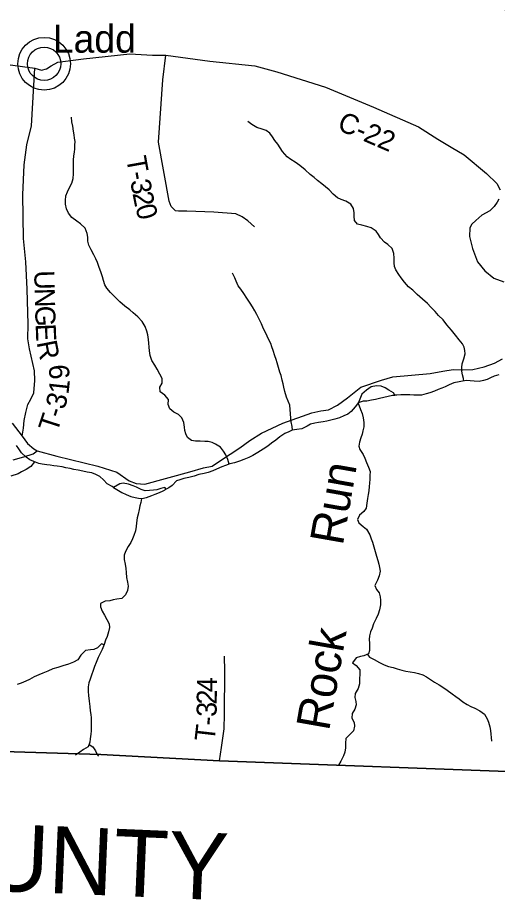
# Model space of a CAD drawing. Extents: x 1578669 to 1989827, y 208020 to 553079.
# Drawn here: x 1774582 to 1781742, y 347821 to 360980 of the extents above; entities that cross this region are included whole.
import ezdxf

# ---------------------------------------------------------------- set-up
doc = ezdxf.new("R2010")
doc.units = 0
for name, color, linetype in [('GM_X_Adjacent_County', 7, 'Continuous'), ('GM_X_Adjacent_County_Text', 7, 'Continuous'), ('GM_X_County', 7, 'Continuous'), ('GM_X_County_Road', 7, 'Continuous'), ('GM_X_County_Road_Text', 7, 'Continuous'), ('GM_X_Minor_River', 7, 'Continuous'), ('GM_X_Minor_River_Text', 7, 'Continuous'), ('GM_X_Township', 7, 'Continuous'), ('GM_X_Township_Road', 7, 'Continuous'), ('GM_X_Township_Road_Text', 7, 'Continuous'), ('GM_X_Unincorporated', 7, 'Continuous'), ('GM_X_Unincorporated_Location', 7, 'Continuous'), ('GM_X_Unincorporated_Text', 7, 'Continuous')]:
    doc.layers.add(name, color=color, linetype=linetype)

msp = doc.modelspace()

# ---------------------------------------------------------------- linework, layer by layer
at = {"layer": 'GM_X_Adjacent_County'}
msp.add_lwpolyline([(1771775, 350107), (1775822, 349984), (1777594, 349890), (1782423, 349710)], dxfattribs=at)
at = {"layer": 'GM_X_County'}
msp.add_lwpolyline([(1782423, 349710), (1777594, 349890), (1775822, 349984), (1771775, 350107)], dxfattribs=at)
at = {"layer": 'GM_X_County_Road'}
for points in [[(1774362, 360289), (1774838, 360225), (1774939, 360195), (1775012, 360218), (1775085, 360260), (1775180, 360315), (1775564, 360363), (1776256, 360441), (1776595, 360422), (1776794, 360418), (1777452, 360331), (1778122, 360260), (1778451, 360172), (1779178, 359940), (1779891, 359642), (1780563, 359349), (1780851, 359167), (1781051, 359047), (1781247, 358934), (1781582, 358654), (1781733, 358504), (1781786, 358411)], [(1781765, 358271), (1781741, 358225), (1781694, 358161), (1781631, 358097), (1781510, 358032), (1781419, 357953), (1781362, 357899), (1781329, 357843), (1781328, 357713), (1781369, 357536), (1781445, 357338), (1781553, 357199), (1781688, 357093), (1781838, 357039)]]:
    msp.add_lwpolyline(points, dxfattribs=at)
at = {"layer": 'GM_X_Minor_River'}
for points in [[(1777737, 354316), (1777739, 354316), (1777721, 354385), (1777690, 354455), (1777654, 354508), (1777609, 354570), (1777537, 354615), (1777483, 354639), (1777425, 354654), (1777375, 354654), (1777307, 354659), (1777239, 354659), (1777175, 354668), (1777117, 354715), (1777092, 354767), (1777076, 354819), (1777075, 354869), (1777063, 354938), (1777032, 355008), (1776982, 355059), (1776914, 355093), (1776853, 355142), (1776827, 355208), (1776832, 355280), (1776780, 355345), (1776707, 355394), (1776705, 355464), (1776740, 355524), (1776738, 355596), (1776705, 355660), (1776665, 355733), (1776628, 355795), (1776586, 355864), (1776561, 355936), (1776550, 356007), (1776546, 356061), (1776539, 356123), (1776535, 356177), (1776526, 356247), (1776512, 356302), (1776487, 356372), (1776443, 356447), (1776376, 356517), (1776308, 356576), (1776256, 356617), (1776181, 356675), (1776105, 356740), (1776034, 356811), (1775966, 356876), (1775913, 356942), (1775885, 356993), (1775864, 357057), (1775848, 357111), (1775825, 357188), (1775801, 357252), (1775772, 357324), (1775750, 357379), (1775721, 357441), (1775679, 357514), (1775644, 357584), (1775632, 357646), (1775629, 357705), (1775621, 357759), (1775588, 357837), (1775520, 357902), (1775467, 357941), (1775393, 357999), (1775339, 358062), (1775310, 358128), (1775297, 358195), (1775295, 358253), (1775302, 358321), (1775324, 358381), (1775351, 358433), (1775389, 358511), (1775410, 358579), (1775416, 358649), (1775415, 358719), (1775416, 358783), (1775414, 358851), (1775423, 358919), (1775433, 358974), (1775436, 359024), (1775438, 359076), (1775439, 359130), (1775431, 359182), (1775425, 359232), (1775416, 359286), (1775404, 359359), (1775393, 359425), (1775385, 359493)], [(1781240, 355557), (1781234, 355597), (1781222, 355649), (1781211, 355703), (1781211, 355759), (1781219, 355813), (1781240, 355889), (1781259, 355962), (1781255, 356014), (1781244, 356064), (1781222, 356114), (1781172, 356171), (1781119, 356241), (1781055, 356316), (1780986, 356397), (1780933, 356468), (1780861, 356534), (1780813, 356593), (1780748, 356660), (1780698, 356716), (1780627, 356781), (1780547, 356848), (1780480, 356912), (1780418, 356961), (1780355, 357030), (1780305, 357096), (1780269, 357147), (1780226, 357215), (1780208, 357266), (1780203, 357320), (1780201, 357392), (1780198, 357462), (1780173, 357533), (1780107, 357595), (1780055, 357630), (1780000, 357694), (1779968, 357745), (1779931, 357795), (1779859, 357844), (1779793, 357865), (1779719, 357883), (1779653, 357898), (1779609, 357952), (1779604, 358017), (1779604, 358067), (1779597, 358133), (1779555, 358197), (1779478, 358240), (1779410, 358265), (1779356, 358291), (1779290, 358346), (1779231, 358409), (1779179, 358455), (1779123, 358500), (1779058, 358548), (1779006, 358595), (1778950, 358640), (1778871, 358710), (1778795, 358771), (1778724, 358824), (1778662, 358861), (1778604, 358905), (1778535, 358984), (1778501, 359036), (1778464, 359091), (1778422, 359147), (1778384, 359200), (1778345, 359254), (1778291, 359295), (1778233, 359315), (1778151, 359340), (1778078, 359385), (1778018, 359429)], [(1778685, 354824), (1778677, 354878), (1778665, 354948), (1778660, 355001), (1778656, 355065), (1778651, 355133), (1778645, 355197), (1778622, 355258), (1778596, 355318), (1778571, 355400), (1778557, 355463), (1778544, 355517), (1778532, 355569), (1778515, 355639), (1778497, 355690), (1778474, 355758), (1778456, 355826), (1778441, 355877), (1778423, 355931), (1778398, 356011), (1778376, 356066), (1778359, 356116), (1778331, 356174), (1778307, 356227), (1778282, 356281), (1778254, 356335), (1778223, 356408), (1778182, 356490), (1778154, 356549), (1778120, 356603), (1778089, 356662), (1778053, 356718), (1778004, 356795), (1777956, 356863), (1777913, 356930), (1777875, 356980), (1777844, 357047), (1777822, 357097), (1777791, 357165)], [(1781765, 355649), (1781693, 355629), (1781639, 355605), (1781589, 355581), (1781536, 355563), (1781468, 355548), (1781398, 355554), (1781334, 355562), (1781284, 355564), (1781224, 355554), (1781174, 355547), (1781093, 355529), (1781023, 355499), (1780963, 355471), (1780913, 355451), (1780859, 355429), (1780805, 355406), (1780732, 355382), (1780680, 355364), (1780608, 355348), (1780552, 355344), (1780496, 355347), (1780434, 355351), (1780350, 355353), (1780299, 355351), (1780243, 355348), (1780213, 355346)], [(1780213, 355346), (1780193, 355379), (1780121, 355422), (1780069, 355454), (1780009, 355479), (1779939, 355487), (1779859, 355470), (1779788, 355422), (1779720, 355363), (1779670, 355237)], [(1779670, 355237), (1779744, 355259), (1779794, 355263), (1779862, 355275), (1779924, 355287), (1779983, 355300)], [(1779983, 355300), (1780111, 355332), (1780175, 355344), (1780213, 355346)], [(1779670, 355237), (1779620, 355171), (1779561, 355101), (1779509, 355063), (1779453, 355038), (1779387, 355010), (1779316, 354990), (1779256, 354974), (1779198, 354956), (1779142, 354946), (1779072, 354939), (1779020, 354929), (1778953, 354911), (1778903, 354883), (1778823, 354845), (1778751, 354834), (1778681, 354824), (1778628, 354800), (1778570, 354772), (1778496, 354722), (1778438, 354676), (1778373, 354630), (1778315, 354586), (1778247, 354539), (1778168, 354489), (1778090, 354445), (1778034, 354415), (1777960, 354385), (1777891, 354363), (1777817, 354336), (1777749, 354320), (1777685, 354298), (1777629, 354276), (1777548, 354240), (1777496, 354216), (1777426, 354193), (1777366, 354179), (1777286, 354161), (1777215, 354139), (1777135, 354117), (1777061, 354100), (1777003, 354082), (1776951, 354068), (1776890, 353998), (1776838, 353964), (1776801, 353944)], [(1779663, 355229), (1779700, 355134), (1779725, 355070), (1779737, 355006), (1779750, 354937), (1779748, 354873), (1779735, 354815), (1779723, 354765), (1779702, 354707), (1779682, 354643), (1779673, 354585), (1779691, 354533), (1779738, 354462), (1779766, 354406), (1779789, 354340), (1779821, 354273), (1779842, 354205), (1779840, 354147), (1779837, 354090), (1779833, 354032), (1779830, 353982), (1779822, 353918), (1779813, 353864), (1779803, 353802), (1779796, 353734), (1779782, 353662), (1779747, 353608), (1779683, 353554), (1779656, 353490), (1779676, 353440), (1779737, 353384), (1779789, 353347), (1779838, 353264), (1779860, 353204), (1779878, 353150), (1779899, 353081), (1779920, 353015), (1779940, 352943), (1779959, 352880), (1779971, 352824), (1779985, 352774), (1779992, 352720), (1779976, 352652), (1779951, 352584), (1779914, 352506), (1779940, 352447), (1779977, 352397), (1779993, 352337), (1779998, 352287), (1779996, 352218), (1779981, 352140), (1779961, 352076), (1779934, 352012), (1779895, 351934), (1779873, 351871), (1779848, 351813), (1779834, 351753), (1779829, 351700), (1779835, 351644), (1779834, 351584), (1779832, 351534), (1779820, 351484), (1779751, 351456), (1779701, 351447), (1779633, 351425), (1779582, 351350), (1779634, 351311), (1779689, 351248), (1779691, 351186), (1779686, 351110), (1779684, 351040), (1779663, 350968), (1779622, 350894), (1779616, 350836), (1779629, 350776), (1779637, 350724), (1779616, 350660), (1779574, 350594), (1779569, 350528), (1779607, 350463), (1779612, 350405), (1779596, 350337), (1779535, 350277), (1779481, 350222), (1779476, 350151), (1779477, 350083), (1779467, 350017), (1779444, 349961), (1779404, 349885), (1779369, 349825)], [(1776013, 353969), (1775991, 353983), (1775919, 354024), (1775863, 354084), (1775809, 354132), (1775749, 354163), (1775691, 354185), (1775621, 354199), (1775557, 354212), (1775487, 354226), (1775419, 354238), (1775365, 354250), (1775303, 354263), (1775247, 354275), (1775174, 354285), (1775120, 354293), (1775068, 354300), (1775018, 354306), (1774950, 354316), (1774900, 354328), (1774822, 354357), (1774764, 354383), (1774708, 354423), (1774642, 354484), (1774602, 354544), (1774567, 354594)], [(1774836, 354352), (1774777, 354279), (1774711, 354239), (1774640, 354200), (1774588, 354174), (1774480, 354139)], [(1776801, 353944), (1776777, 353966), (1776721, 353952), (1776662, 353934), (1776608, 353927), (1776548, 353923), (1776484, 353920), (1776426, 353938), (1776358, 353971), (1776304, 353993), (1776237, 354020), (1776157, 354031), (1776107, 354023), (1776013, 353969)], [(1776013, 353969), (1776063, 353937), (1776135, 353894), (1776203, 353862), (1776271, 353836), (1776337, 353819), (1776387, 353807), (1776437, 353805), (1776507, 353819), (1776583, 353847), (1776637, 353866), (1776698, 353894), (1776756, 353920), (1776801, 353944)], [(1776431, 353805), (1776423, 353744), (1776408, 353692), (1776398, 353638), (1776379, 353572), (1776367, 353516), (1776358, 353442), (1776353, 353388), (1776341, 353319), (1776318, 353251), (1776298, 353200), (1776271, 353148), (1776233, 353088), (1776192, 353014), (1776172, 352956), (1776171, 352892), (1776185, 352826), (1776196, 352757), (1776204, 352701), (1776209, 352623), (1776220, 352555), (1776232, 352496), (1776221, 352432), (1776191, 352364), (1776138, 352311), (1776064, 352301), (1776010, 352290), (1775958, 352276), (1775888, 352271), (1775821, 352239), (1775817, 352189), (1775842, 352121), (1775878, 352062), (1775915, 351998), (1775947, 351931), (1775952, 351879), (1775938, 351813), (1775917, 351745), (1775895, 351689), (1775876, 351625), (1775842, 351551), (1775815, 351489), (1775786, 351429), (1775754, 351357), (1775729, 351295), (1775707, 351237), (1775684, 351167), (1775664, 351109), (1775647, 351051), (1775635, 350993), (1775634, 350923), (1775638, 350865), (1775651, 350779), (1775662, 350698), (1775666, 350636), (1775673, 350580), (1775681, 350530), (1775680, 350394), (1775681, 350339), (1775677, 350289), (1775664, 350217), (1775662, 350165), (1775635, 350097), (1775567, 350056), (1775512, 350016), (1775444, 349971)], [(1775874, 351620), (1775834, 351633), (1775774, 351574), (1775721, 351548), (1775669, 351547), (1775597, 351535), (1775524, 351464), (1775480, 351394), (1775417, 351362), (1775339, 351333), (1775257, 351305), (1775183, 351282), (1775108, 351262), (1775032, 351227), (1774960, 351197), (1774897, 351174), (1774831, 351140), (1774757, 351105), (1774704, 351079), (1774636, 351048), (1774576, 351026)], [(1779804, 351478), (1779835, 351438), (1779905, 351401), (1779983, 351354), (1780050, 351322), (1780116, 351299), (1780186, 351280), (1780248, 351262), (1780316, 351243), (1780376, 351229), (1780506, 351208), (1780564, 351193), (1780632, 351172), (1780686, 351144), (1780743, 351103), (1780805, 351063), (1780871, 351022), (1780927, 350990), (1780994, 350945), (1781068, 350888), (1781120, 350850), (1781174, 350813), (1781227, 350770), (1781291, 350728), (1781347, 350701), (1781405, 350677), (1781480, 350636), (1781548, 350583), (1781590, 350517), (1781611, 350465), (1781629, 350396), (1781640, 350342), (1781646, 350288), (1781647, 350238), (1781653, 350181)], [(1775649, 350132), (1775703, 350099), (1775743, 350036), (1775770, 349982), (1775788, 349958)]]:
    msp.add_lwpolyline(points, dxfattribs=at)
at = {"layer": 'GM_X_Township'}
msp.add_lwpolyline([(1782423, 349710), (1777594, 349890), (1775822, 349984), (1771775, 350107)], dxfattribs=at)
at = {"layer": 'GM_X_Township_Road'}
for points in [[(1778115, 357859), (1778017, 357948), (1777931, 358009), (1777837, 358054), (1777512, 358078), (1777108, 358092), (1776984, 358093), (1776936, 358099), (1776872, 358160), (1776842, 358241), (1776684, 359120), (1776748, 360051), (1776794, 360418)], [(1774651, 354733), (1774668, 354851), (1774679, 354970), (1774704, 355086), (1774736, 355206), (1774779, 355288), (1774822, 355382), (1774841, 355566), (1774835, 355707), (1774809, 355820), (1774759, 356035), (1774736, 356186), (1774738, 356404), (1774723, 356929), (1774703, 357338), (1774670, 357686), (1774661, 358337), (1774682, 358784), (1774718, 359081), (1774787, 359363), (1774838, 360225)], [(1774518, 354382), (1774677, 354428), (1774816, 354469), (1774875, 354517), (1775167, 354437), (1775781, 354284), (1776064, 354195), (1776246, 354069), (1776350, 354026), (1776479, 354016), (1777151, 354202), (1777355, 354261), (1777484, 354284), (1777611, 354369), (1777900, 354558), (1778050, 354671), (1778222, 354778), (1778542, 354928), (1778974, 355080), (1779105, 355113), (1779221, 355128), (1779358, 355197), (1779504, 355308), (1779702, 355464), (1780013, 355570), (1780182, 355622), (1780741, 355669), (1780930, 355705), (1781081, 355728), (1781228, 355724), (1781376, 355729), (1781546, 355771), (1781699, 355822), (1781820, 355889)], [(1774501, 354927), (1774651, 354733), (1774727, 354624), (1774823, 354546), (1774875, 354517)], [(1777594, 349890), (1777623, 350086), (1777667, 350365), (1777671, 350584), (1777675, 351226), (1777671, 351453)]]:
    msp.add_lwpolyline(points, dxfattribs=at)
at = {"layer": 'GM_X_Unincorporated'}
for radius in [393, 249]:
    msp.add_circle((1774978, 360292), radius, dxfattribs=at)
at = {"layer": 'GM_X_Unincorporated_Location'}
msp.add_line((1774978, 360292), (1774978, 360292), dxfattribs=at)

# ---------------------------------------------------------------- texts
at = {"layer": 'GM_X_Adjacent_County_Text'}
msp.add_text('SCIOTO COUNTY', height=1000, rotation=357.5724, dxfattribs=at).set_placement((1766567, 348277))
at = {"layer": 'GM_X_County_Road_Text'}
msp.add_text('C-22', height=300, rotation=336.7563, dxfattribs=at).set_placement((1779336, 359314))
at = {"layer": 'GM_X_Minor_River_Text'}
for s, rotation, p in [('Creek', 326.8717, (1781158, 361534)), ('Run', 80.0022, (1779434, 353090)), ('Rock', 80.0021, (1779229, 350323))]:
    msp.add_text(s, height=500, rotation=rotation, dxfattribs=at).set_placement(p)
at = {"layer": 'GM_X_Township_Road_Text'}
for s, rotation, p in [('T', 280.1281, (1776200, 358887)), ('-', 280.1808, (1776240, 358666)), ('3', 280.3504, (1776261, 358544)), ('2', 281.0484, (1776295, 358358)), ('0', 284.9961, (1776336, 358155)), ('U', 271.5047, (1774829, 357205)), ('N', 271.501, (1774836, 356941)), ('G', 271.5212, (1774842, 356677)), ('E', 272.2875, (1774850, 356408)), ('R', 281.1986, (1774865, 356134)), ('9', 94.416, (1775361, 355593)), ('1', 83.7843, (1775340, 355349)), ('3', 74.5951, (1775281, 355119)), ('T', 71.9567, (1775170, 354774)), ('-', 72.4079, (1775241, 354990)), ('4', 89.5853, (1777556, 350912)), ('2', 89.4751, (1777554, 350728)), ('3', 89.2678, (1777552, 350544)), ('T', 83.3745, (1777519, 350166)), ('-', 87.6684, (1777546, 350412))]:
    msp.add_text(s, height=300, rotation=rotation, dxfattribs=at).set_placement(p)
at = {"layer": 'GM_X_Unincorporated_Text'}
msp.add_text('Ladd', height=417, rotation=0, dxfattribs=at).set_placement((1775107, 360457))

doc.saveas('drawing.dxf')
